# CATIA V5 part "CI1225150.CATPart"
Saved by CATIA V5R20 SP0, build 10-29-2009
Part number: CO1225150_ASM
Bounding box of the stored display mesh (mm): x -24 to 24, y -20.022 to 184.5, z -27.733 to 28.158
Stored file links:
  C:\Users\Raffaele\Desktop\3D X SITO CF\BOLEX\19-INCLINED ASSEMBLY REF_CI\CI1225150.CATPart

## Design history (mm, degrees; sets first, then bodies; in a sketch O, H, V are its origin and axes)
Set1
  DatumSurface1 to DatumSurface16 "MANIFOLD_SOLID_BREP #393"
  DatumSurface17 to DatumSurface39 "MANIFOLD_SOLID_BREP #1138"
Body1 (main body)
